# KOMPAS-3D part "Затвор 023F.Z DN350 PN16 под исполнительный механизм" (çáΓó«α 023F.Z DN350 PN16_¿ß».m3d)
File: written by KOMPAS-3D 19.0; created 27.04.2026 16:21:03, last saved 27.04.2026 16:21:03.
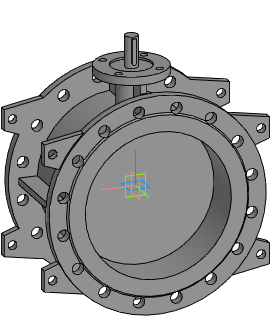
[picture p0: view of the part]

Document properties: Автор: Евгений; Полное имя файла: Z:\3.Личные\kachalov\3d для проектировщиков\1.7 Тип 023F.Z Затвор дисковый поворотный фланцевый с двумя эксцентриками\Затвор 023F.Z DN200-DN1600_исп\_stp_Затвор 023F.Z DN200-DN1600_исп\Затвор 023F.Z DN350 PN16_исп.m3d

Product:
- Part/product: Затвор 023F.Z DN350 PN16 под исполнительный механизм

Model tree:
1. Операция без истории:1  (labels: Затвор 023F.Z DN350 PN16 под исполнительный механизм)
